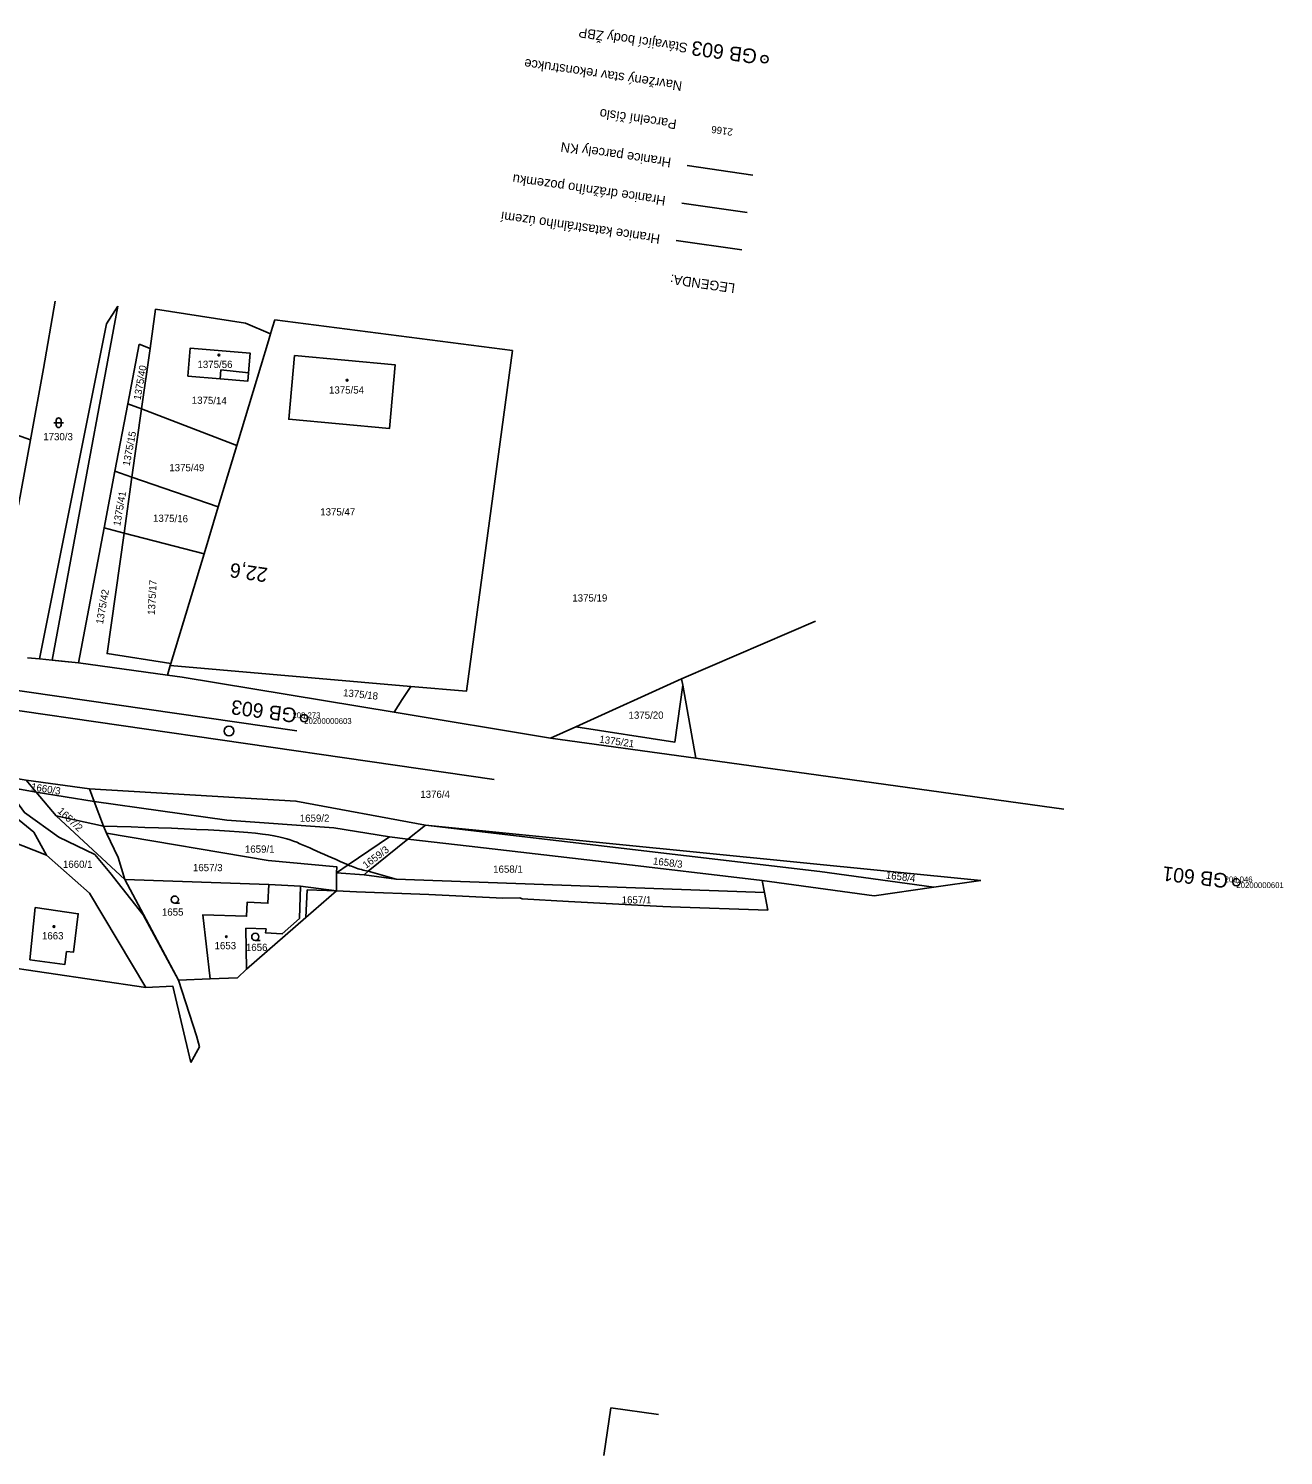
# Model space of a CAD drawing. Extents: x -757909 to -757266, y -1060303 to -1059942.
# Drawn here: x -757525.7 to -757265.9, y -1060302.6 to -1060007 of the extents above; entities that cross this region are included whole.
import ezdxf

# ---------------------------------------------------------------- set-up
doc = ezdxf.new("R2010")
doc.units = 0
for name, color, linetype in [('_hektaky', 7, 'Continuous'), ('_SO 102 hektometry', 7, 'Continuous'), ('Legenda 1', 7, 'Continuous'), ('Legenda 2', 7, 'Continuous'), ('Level 53', 7, 'Continuous'), ('Vrstva 1', 7, 'Continuous'), ('Vrstva 53', 7, 'Continuous'), ('Vrstva 55', 7, 'Continuous'), ('Vrstva 56', 7, 'Continuous'), ('Vrstva 57', 7, 'Continuous'), ('Vrstva 58', 7, 'Continuous'), ('Vrstva 59', 7, 'Continuous'), ('Vrstva 60', 7, 'Continuous'), ('Vrstva 61', 7, 'Continuous'), ('Vrstva 63', 7, 'Continuous')]:
    doc.layers.add(name, color=color, linetype=linetype)

msp = doc.modelspace()

# ---------------------------------------------------------------- linework, layer by layer
at = {"layer": '_SO 102 hektometry'}
msp.add_circle((-757484.25, -1060152.51), 1, dxfattribs=at)
at = {"layer": 'Legenda 1'}
for q in [(-757406.6, -1060302.59), (-757395.28, -1060294.12)]:
    msp.add_line((-757405.18, -1060292.69), q, dxfattribs=at)
at = {"layer": 'Level 53'}
msp.add_line((-757376.93, -1060045.09), (-757390.49, -1060043.13), dxfattribs=at)
at = {"layer": 'Vrstva 1'}
for p, q in [((-757429.32, -1060162.53), (-757720.62, -1060120.47)), ((-757576.18, -1060137.2), (-757470.2, -1060152.45))]:
    msp.add_line(p, q, dxfattribs=at)
at = {"layer": 'Vrstva 53'}
for points in [[(-757328.56, -1060183.46), (-757338.29, -1060184.85), (-757361.91, -1060181.63), (-757443.58, -1060171.99), (-757470.38, -1060167.04), (-757513.1, -1060164.5), (-757526.21, -1060162.71), (-757533.6, -1060161.43), (-757535.01, -1060161.18), (-757542.9, -1060160.49), (-757543.88, -1060160.4), (-757632.1, -1060146.3), (-757634.26, -1060145.96), (-757635.44, -1060145.86), (-757686.64, -1060138.39), (-757693.18, -1060137.43), (-757732.62, -1060131.67), (-757793.56, -1060122.78), (-757866, -1060118.97)], [(-757525.99, -1060137.35), (-757523.49, -1060137.59), (-757520.85, -1060137.84), (-757515.4, -1060138.37), (-757496.99, -1060140.91), (-757493.93, -1060141.33), (-757450.04, -1060148.6), (-757417.66, -1060153.97), (-757412.43, -1060151.61), (-757391.89, -1060154.81), (-757390.25, -1060143), (-757387.56, -1060158.16)], [(-757509.58, -1060173.65), (-757510.26, -1060172.2), (-757512.14, -1060167.1), (-757484.68, -1060170.98), (-757462.52, -1060172.6), (-757450.99, -1060174.46), (-757459.56, -1060180.26), (-757461.95, -1060181.88), (-757461.94, -1060180.64), (-757476.1, -1060179.3), (-757509.58, -1060173.65)]]:
    msp.add_lwpolyline(points, dxfattribs=at)
at = {"layer": 'Vrstva 55'}
for p, q in [((-757375.79, -1060037.35), (-757389.35, -1060035.39)), ((-757378.07, -1060052.83), (-757391.63, -1060050.87)), ((-757522.65, -1060077.4), (-757520.23, -1060063.47)), ((-757499.45, -1060065.15), (-757500.59, -1060073.29)), ((-757480.83, -1060068), (-757499.45, -1060065.15)), ((-757475.63, -1060070.26), (-757480.83, -1060068)), ((-757475.21, -1060068.86), (-757475.63, -1060070.26)), ((-757474.75, -1060067.35), (-757475.21, -1060068.86)), ((-757425.51, -1060073.71), (-757474.75, -1060067.35)), ((-757525.35, -1060092.2), (-757579.91, -1060072.75)), ((-757502.84, -1060072.35), (-757505.19, -1060084.71)), ((-757500.59, -1060073.29), (-757502.84, -1060072.35)), ((-757500.59, -1060073.29), (-757502.35, -1060085.79)), ((-757525.35, -1060092.2), (-757522.65, -1060077.4)), ((-757505.19, -1060084.71), (-757507.85, -1060098.68)), ((-757502.35, -1060085.79), (-757505.19, -1060084.71)), ((-757504.33, -1060099.89), (-757502.35, -1060085.79)), ((-757502.35, -1060085.79), (-757482.61, -1060093.33)), ((-757527.8, -1060105.72), (-757525.35, -1060092.2)), ((-757482.61, -1060093.33), (-757486.45, -1060106.04)), ((-757507.85, -1060098.68), (-757510.09, -1060110.45)), ((-757507.85, -1060098.68), (-757504.33, -1060099.89)), ((-757504.33, -1060099.89), (-757505.97, -1060111.52)), ((-757486.45, -1060106.04), (-757504.33, -1060099.89)), ((-757486.45, -1060106.04), (-757489.4, -1060115.81)), ((-757510.09, -1060110.45), (-757515.4, -1060138.37)), ((-757510.09, -1060110.45), (-757505.97, -1060111.52)), ((-757505.97, -1060111.52), (-757489.4, -1060115.81)), ((-757489.4, -1060115.81), (-757496.27, -1060138.53)), ((-757515.4, -1060138.37), (-757496.99, -1060140.91)), ((-757496.4, -1060138.94), (-757496.99, -1060140.91)), ((-757496.27, -1060138.53), (-757496.4, -1060138.94)), ((-757496.4, -1060138.94), (-757446.57, -1060143.26)), ((-757412.43, -1060151.61), (-757390.54, -1060141.71)), ((-757390.25, -1060143), (-757390.54, -1060141.71)), ((-757387.56, -1060158.16), (-757390.25, -1060143)), ((-757450.04, -1060148.6), (-757417.66, -1060153.97)), ((-757417.66, -1060153.97), (-757412.43, -1060151.61)), ((-757417.66, -1060153.97), (-757387.56, -1060158.16)), ((-757387.56, -1060158.16), (-757311.39, -1060168.71)), ((-757526.21, -1060162.71), (-757513.1, -1060164.5)), ((-757513.1, -1060164.5), (-757512.14, -1060167.1)), ((-757443.58, -1060171.99), (-757447.18, -1060174.91)), ((-757443.58, -1060171.99), (-757328.56, -1060183.46)), ((-757507.2, -1060178.7), (-757509.58, -1060173.65)), ((-757450.99, -1060174.46), (-757447.18, -1060174.91)), ((-757505.82, -1060183.25), (-757507.2, -1060178.7)), ((-757461.95, -1060181.88), (-757461.97, -1060185.63)), ((-757456.27, -1060182.28), (-757461.95, -1060181.88)), ((-757449.6, -1060183.18), (-757456.27, -1060182.28)), ((-757475.98, -1060184.31), (-757505.82, -1060183.25)), ((-757505.82, -1060183.25), (-757494.7, -1060204.13)), ((-757469.46, -1060184.66), (-757475.98, -1060184.31)), ((-757461.97, -1060185.63), (-757469.46, -1060184.66)), ((-757373.35, -1060185.99), (-757373.86, -1060183.46)), ((-757350.67, -1060186.62), (-757373.86, -1060183.46)), ((-757338.29, -1060184.85), (-757350.67, -1060186.62)), ((-757328.56, -1060183.46), (-757338.29, -1060184.85)), ((-757468.3, -1060191.14), (-757461.97, -1060185.63)), ((-757461.97, -1060185.63), (-757457.81, -1060185.8)), ((-757457.81, -1060185.8), (-757442.84, -1060186.4)), ((-757427.56, -1060187.16), (-757442.84, -1060186.4)), ((-757423.99, -1060187.1), (-757427.56, -1060187.16)), ((-757372.63, -1060189.61), (-757373.35, -1060185.99)), ((-757480.62, -1060201.84), (-757468.3, -1060191.14)), ((-757372.63, -1060189.61), (-757392.78, -1060188.96)), ((-757553.73, -1060197.99), (-757501.45, -1060205.62)), ((-757482.5, -1060203.63), (-757480.62, -1060201.84)), ((-757488.16, -1060203.86), (-757494.7, -1060204.13)), ((-757482.5, -1060203.63), (-757488.16, -1060203.86)), ((-757492.15, -1060221.2), (-757490.36, -1060217.94))]:
    msp.add_line(p, q, dxfattribs=at)
for points in [[(-757475.63, -1060070.26), (-757476.07, -1060071.71), (-757479.24, -1060082.21), (-757482.61, -1060093.33)], [(-757486.06, -1060079.54), (-757480.34, -1060080.05), (-757480.18, -1060078.28), (-757479.84, -1060074.24), (-757492.3, -1060073.2), (-757492.76, -1060078.99), (-757486.06, -1060079.54)], [(-757470.67, -1060074.74), (-757449.81, -1060076.66), (-757451.01, -1060089.85), (-757471.85, -1060087.93), (-757470.67, -1060074.74)], [(-757446.57, -1060143.26), (-757435.09, -1060144.26), (-757425.51, -1060073.71)], [(-757505.97, -1060111.52), (-757509.48, -1060136.47), (-757496.27, -1060138.53)], [(-757390.54, -1060141.71), (-757390.04, -1060141.48), (-757362.82, -1060129.73)], [(-757515.4, -1060138.37), (-757518.94, -1060138.03), (-757520.85, -1060137.84), (-757523.49, -1060137.59), (-757525.99, -1060137.35)], [(-757496.99, -1060140.91), (-757493.93, -1060141.33), (-757450.04, -1060148.6)], [(-757450.04, -1060148.6), (-757448.35, -1060146), (-757446.57, -1060143.26)], [(-757412.43, -1060151.61), (-757391.89, -1060154.81), (-757390.25, -1060143)], [(-757535.4, -1060164.4), (-757534.05, -1060166.5), (-757527.72, -1060171), (-757524.67, -1060173.45), (-757522.06, -1060178.2)], [(-757530.47, -1060164.08), (-757526.6, -1060169.42), (-757519.47, -1060174.52), (-757512.04, -1060178.07), (-757508.94, -1060181.82), (-757502, -1060190.6), (-757494.7, -1060204.13)], [(-757512.14, -1060167.1), (-757524.18, -1060165.15), (-757527.62, -1060164.59), (-757530.47, -1060164.08)], [(-757513.1, -1060164.5), (-757470.38, -1060167.04), (-757443.58, -1060171.99)], [(-757450.99, -1060174.46), (-757462.52, -1060172.6), (-757484.68, -1060170.98), (-757512.14, -1060167.1)], [(-757509.58, -1060173.65), (-757510.26, -1060172.2), (-757512.14, -1060167.1)], [(-757541.4, -1060170.7), (-757539.76, -1060171.25), (-757522.06, -1060178.2)], [(-757338.29, -1060184.85), (-757361.91, -1060181.63), (-757443.58, -1060171.99)], [(-757461.95, -1060181.88), (-757461.94, -1060180.64), (-757476.1, -1060179.3), (-757509.58, -1060173.65)], [(-757461.95, -1060181.88), (-757459.56, -1060180.26), (-757450.99, -1060174.46)], [(-757447.18, -1060174.91), (-757455.39, -1060181.56), (-757456.27, -1060182.28)], [(-757373.86, -1060183.46), (-757405.36, -1060179.78), (-757434.52, -1060176.38), (-757447.18, -1060174.91)], [(-757522.06, -1060178.2), (-757513.1, -1060186.11), (-757501.45, -1060205.62)], [(-757475.98, -1060184.31), (-757476.19, -1060188.18), (-757480.46, -1060187.96), (-757480.61, -1060190.87), (-757489.65, -1060190.56), (-757488.16, -1060203.86)], [(-757480.62, -1060201.84), (-757480.75, -1060193.37), (-757476.57, -1060193.52), (-757476.69, -1060194.3), (-757473.22, -1060194.56), (-757469.64, -1060191.34), (-757469.46, -1060184.66)], [(-757373.35, -1060185.99), (-757375.27, -1060185.92), (-757449.6, -1060183.18)], [(-757413.91, -1060187.83), (-757423.52, -1060187.25), (-757423.99, -1060187.1)], [(-757392.78, -1060188.96), (-757394.39, -1060188.87), (-757413.91, -1060187.83)], [(-757525.5, -1060199.9), (-757518.26, -1060200.9), (-757517.87, -1060198.2), (-757516.44, -1060198.33), (-757515.46, -1060190.37), (-757524.35, -1060189.08), (-757525.5, -1060199.9)], [(-757501.45, -1060205.62), (-757495.89, -1060205.36), (-757492.15, -1060221.2)], [(-757494.7, -1060204.13), (-757490.98, -1060215.68), (-757490.36, -1060217.94)]]:
    msp.add_lwpolyline(points, dxfattribs=at)
at = {"layer": 'Vrstva 56'}
for p, q in [((-757516.7, -1060115.45), (-757507.27, -1060064.51)), ((-757507.27, -1060064.51), (-757509.6, -1060068.17)), ((-757509.6, -1060068.17), (-757518.99, -1060115.13)), ((-757486.06, -1060079.54), (-757485.91, -1060077.7)), ((-757485.91, -1060077.7), (-757480.18, -1060078.28)), ((-757518.99, -1060115.13), (-757523.49, -1060137.59)), ((-757520.85, -1060137.84), (-757516.7, -1060115.45)), ((-757526.21, -1060162.71), (-757524.18, -1060165.15)), ((-757524.18, -1060165.15), (-757520.05, -1060170.1)), ((-757520.05, -1060170.1), (-757505.82, -1060183.25)), ((-757510.26, -1060172.2), (-757520.05, -1060170.1)), ((-757455.39, -1060181.56), (-757449.6, -1060183.18)), ((-757468.07, -1060185.38), (-757468.3, -1060191.14)), ((-757461.97, -1060185.63), (-757468.07, -1060185.38))]:
    msp.add_line(p, q, dxfattribs=at)
for points in [[(-757510.26, -1060172.2), (-757507.38, -1060172.29), (-757504.48, -1060172.38), (-757501.65, -1060172.48), (-757498.87, -1060172.57), (-757496.13, -1060172.67), (-757493.5, -1060172.78), (-757490.97, -1060172.88), (-757488.52, -1060173), (-757486.24, -1060173.12), (-757484.11, -1060173.25), (-757482.11, -1060173.39), (-757480.33, -1060173.53), (-757478.74, -1060173.69), (-757477.31, -1060173.85), (-757476.06, -1060174.03), (-757474.95, -1060174.21), (-757473.95, -1060174.41), (-757473.07, -1060174.62), (-757472.28, -1060174.84), (-757471.54, -1060175.07), (-757470.86, -1060175.32), (-757470.2, -1060175.57), (-757469.55, -1060175.85), (-757468.9, -1060176.13), (-757468.22, -1060176.43), (-757467.51, -1060176.74), (-757466.79, -1060177.06), (-757466.04, -1060177.39), (-757465.27, -1060177.73), (-757464.48, -1060178.07), (-757463.69, -1060178.43), (-757462.87, -1060178.79), (-757462.05, -1060179.15), (-757461.23, -1060179.52), (-757460.39, -1060179.89), (-757459.56, -1060180.26)], [(-757455.39, -1060181.56), (-757455.75, -1060181.49), (-757456.1, -1060181.41), (-757456.46, -1060181.33), (-757456.81, -1060181.23), (-757457.16, -1060181.14), (-757457.51, -1060181.03), (-757457.86, -1060180.92), (-757458.2, -1060180.8), (-757458.55, -1060180.68), (-757458.89, -1060180.54), (-757459.22, -1060180.41), (-757459.56, -1060180.26)]]:
    msp.add_lwpolyline(points, dxfattribs=at)
at = {"layer": 'Vrstva 58'}
for p, q in [((-757520.52, -1060088.64), (-757518.52, -1060088.64)), ((-757520.02, -1060088.14), (-757520.02, -1060089.14)), ((-757519.02, -1060088.14), (-757519.02, -1060089.14)), ((-757495.47, -1060188.19), (-757494.47, -1060188.19)), ((-757478.79, -1060195.9), (-757477.79, -1060195.9))]:
    msp.add_line(p, q, dxfattribs=at)
for centre in [(-757495.47, -1060187.44), (-757478.79, -1060195.15)]:
    msp.add_circle(centre, 0.75, dxfattribs=at)
for centre, start, end in [((-757519.52, -1060088.14), 0, 180), ((-757519.52, -1060089.14), 180, 0)]:
    msp.add_arc(centre, 0.5, start, end, dxfattribs=at)
at = {"layer": 'Vrstva 59'}
for centre in [(-757486.33, -1060074.63), (-757459.78, -1060079.84), (-757520.49, -1060193.01), (-757484.78, -1060195.12)]:
    msp.add_circle(centre, 0.175, dxfattribs=at)
at = {"layer": 'Vrstva 60'}
for p, q in [((-757468.66, -1060149.84), (-757468.66, -1060149.84)), ((-757275.64, -1060183.85), (-757275.64, -1060183.85))]:
    msp.add_line(p, q, dxfattribs=at)
at = {"layer": 'Vrstva 63'}
for p, q in [((-757373.35, -1060013.37), (-757373.35, -1060013.27)), ((-757468.66, -1060149.89), (-757468.66, -1060149.79)), ((-757275.64, -1060183.9), (-757275.64, -1060183.8))]:
    msp.add_line(p, q, dxfattribs=at)
for centre in [(-757373.35, -1060013.32), (-757468.66, -1060149.84), (-757275.64, -1060183.85)]:
    msp.add_circle(centre, 0.756, dxfattribs=at)

# ---------------------------------------------------------------- texts
at = {"layer": '_hektaky'}
msp.add_text('22,6', height=3, rotation=171.8129, dxfattribs=at).set_placement((-757476.09, -1060118.76))
at = {"layer": 'Legenda 2'}
for s, p in [('Stávající body ŽBP', (-757389.17, -1060010.05)), ('Navržený stav rekonstrukce', (-757390.31, -1060017.96)), ('Parcelní číslo', (-757391.45, -1060025.88)), ('Hranice parcely KN', (-757392.59, -1060033.8)), ('Hranice drážního pozemku', (-757393.74, -1060041.72)), ('Hranice katastrálního území', (-757394.88, -1060049.64)), ('LEGENDA:', (-757379.35, -1060059.84))]:
    msp.add_text(s, height=2, rotation=171.7882, dxfattribs=at).set_placement(p)
at = {"layer": 'Vrstva 57'}
for s, rotation, p in [('2166', 171.7882, (-757379.83, -1060027.75)), ('1375/40', 80, (-757502.55, -1060084.03)), ('1375/14', 359, (-757491.96, -1060084.71)), ('1375/15', 79, (-757504.83, -1060097.7)), ('1375/41', 80, (-757506.77, -1060110.13)), ('1375/16', 359, (-757499.99, -1060109.15)), ('1375/42', 80, (-757510.34, -1060130.46)), ('1375/17', 87, (-757499.59, -1060128.49)), ('1375/18', 354, (-757460.68, -1060145.28)), ('1375/21', 352, (-757407.63, -1060154.9)), ('1660/3', 351, (-757525.3, -1060164.76)), ('1657/2', 317, (-757519.86, -1060169.27)), ('1659/3', 37, (-757455.86, -1060181.08)), ('1658/3', 353, (-757396.51, -1060180.14)), ('1658/4', 353, (-757348.29, -1060183.06))]:
    msp.add_text(s, height=1.5, rotation=rotation, dxfattribs=at).set_placement(p)
for s, p in [('1375/56', (-757490.77, -1060077.3)), ('1375/54', (-757463.53, -1060082.61)), ('1730/3', (-757522.7, -1060092.28)), ('1375/49', (-757496.6, -1060098.7)), ('1375/47', (-757465.35, -1060107.86)), ('1375/19', (-757413.15, -1060125.69)), ('1375/20', (-757401.51, -1060149.97)), ('1376/4', (-757444.63, -1060166.36)), ('1659/2', (-757469.58, -1060171.31)), ('1659/1', (-757480.95, -1060177.72)), ('1660/1', (-757518.63, -1060180.86)), ('1657/3', (-757491.71, -1060181.55)), ('1658/1', (-757429.54, -1060181.87)), ('1657/1', (-757402.93, -1060188.24)), ('1655', (-757498.13, -1060190.76)), ('1663', (-757522.97, -1060195.68)), ('1653', (-757487.23, -1060197.72)), ('1656', (-757480.74, -1060198.08))]:
    msp.add_text(s, height=1.5, dxfattribs=at).set_placement(p)
at = {"layer": 'Vrstva 60'}
for s, p in [('20200000603', (-757468.66, -1060151.04)), ('20200000601', (-757275.64, -1060185.05))]:
    msp.add_text(s, height=1.2, dxfattribs=at).set_placement(p)
at = {"layer": 'Vrstva 61'}
for s, p in [('208.273', (-757471.11, -1060149.84)), ('209.046', (-757278.09, -1060183.85))]:
    msp.add_text(s, height=1.2, dxfattribs=at).set_placement(p)
at = {"layer": 'Vrstva 63'}
for s, rotation, p in [('GB 603', 172.1845, (-757374.75, -1060011.36)), ('GB 603', 172.1845, (-757470.06, -1060147.88)), ('GB 601', 173.2695, (-757277.23, -1060182.11))]:
    msp.add_text(s, height=3, rotation=rotation, dxfattribs=at).set_placement(p)

doc.saveas('drawing.dxf')
